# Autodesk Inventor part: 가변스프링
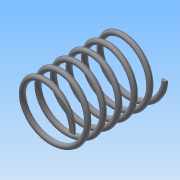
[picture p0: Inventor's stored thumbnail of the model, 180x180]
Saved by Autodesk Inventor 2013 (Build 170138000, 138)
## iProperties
Created: 2018-06
Part Number: 가변스프링
Material: 일반
Document SubType Name: Modeling
Designer: Administrator
Density: 1 g/cm^3
Author: Administrator
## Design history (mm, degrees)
sketch "스케치1"
  geometry: L1 (0, 0)-(22.5, 0); L2 (0, 0)-(0, 73.25); L3 (0, 73.25)-(22.5, 73.25); C1 r 2 at (22.5, 0)
  constraints: 6 end point, 2 perpendicular, 1 centre point, 1 coincident, 1 horizontal
  dimensions: "d0" = 22.5 distance of L1.start L1.end; "d1" = 73.25 distance of L1.start L2.end (derived); "d2" = 22.5 distance of L2.end L3.end; "d3" = 4 diameter of C1
feature "코일1" sketch "스케치1" pitch "d4" = 10; turns "d6" = 6; dims "d5" = 73.25 (= d1), "d7" = 0, angle "d8" = 90 deg, angle "d9" = 90 deg, "d10" = 0, "d11" = 0
sketch "스케치2"
  geometry: L1 (73.25, 30)-(0, 30); L2 (0, 30)-(0, -30); L3 (0, -30)-(73.25, -30); L4 (73.25, -30)-(73.25, 30); 2 further points
  constraints: 8 end point, 2 parallel, 1 coincident, 1 horizontal, 1 midpoint, 1 perpendicular
  dimensions: "d12" = 60 distance of L3.end L1.start; "d15" = 73.25 distance of L2.end L3.end (derived)
extrude "돌출1" sketch "스케치2" stored distance "d16" = 10; taper "d17" = 0 deg
node "솔리드1"
